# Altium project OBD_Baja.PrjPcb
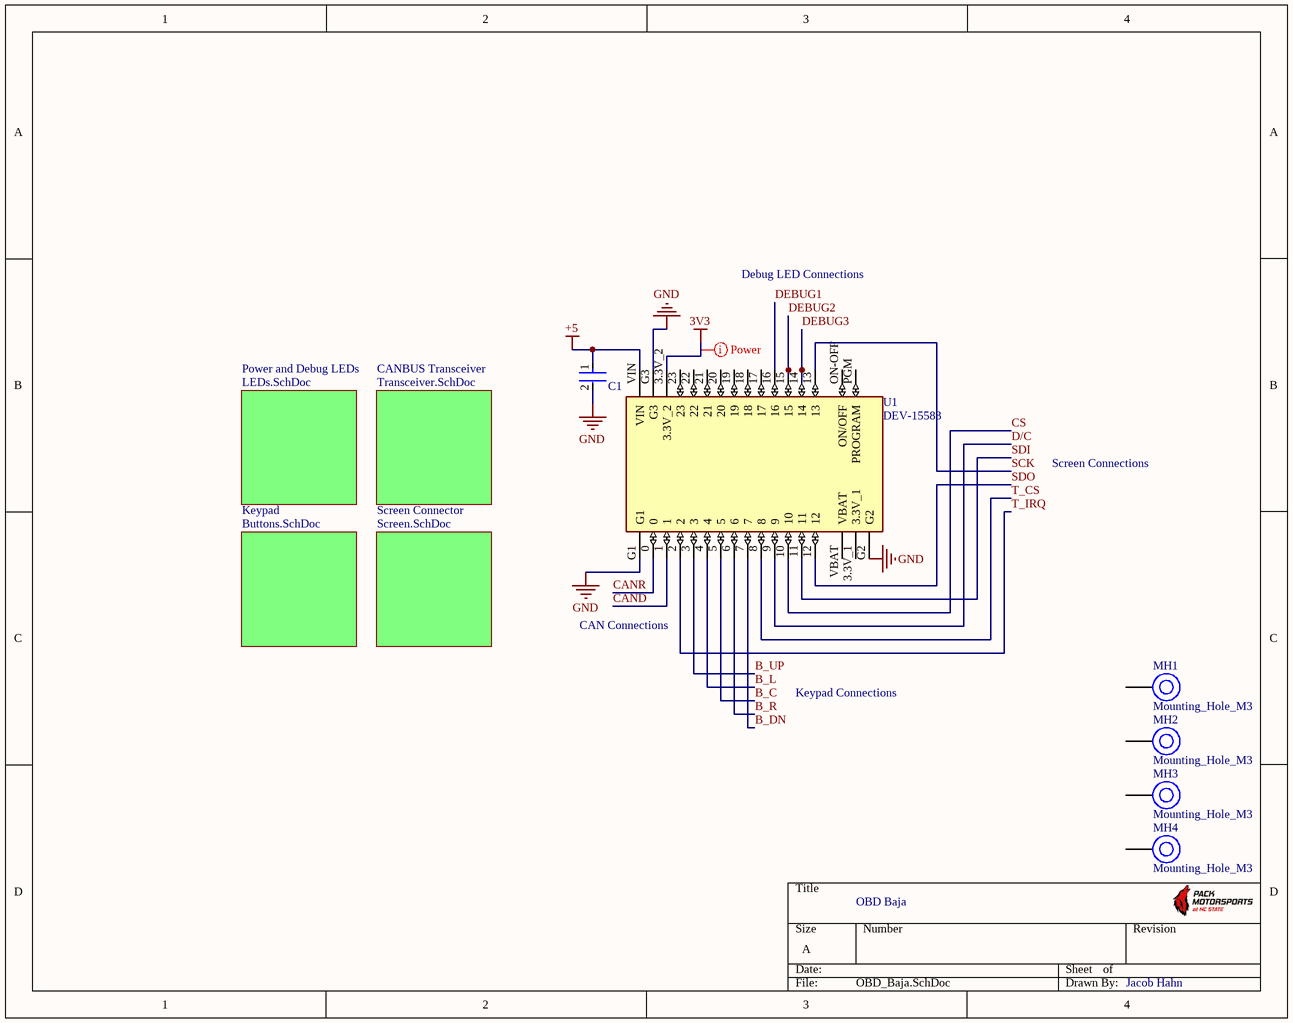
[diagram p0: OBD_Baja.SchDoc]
5 sheets, 34 parts. Net scope: global (net labels, ports and power ports of the same name join across sheets).
Board file: OBD_Baja.PcbDoc
Sheets:
  OBD_Baja.SchDoc
    CANBUS Transceiver = Transceiver.SchDoc
    Power and Debug LEDs = LEDs.SchDoc
    Keypad = Buttons.SchDoc
    Screen Connector = Screen.SchDoc

## Sheet OBD_Baja.SchDoc
size A; SheetNumber: 1; SheetTotal: 5

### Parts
C1  CL21B104KACNNNC  [FP-CL21-IPC_C]  (value not drawn)
MH1  Mounting_Hole_M3  [Mounting_Hole_M3]  (no BOM)
MH2  Mounting_Hole_M3  [Mounting_Hole_M3]  (no BOM)
MH3  Mounting_Hole_M3  [Mounting_Hole_M3]  (no BOM)
MH4  Mounting_Hole_M3  [Mounting_Hole_M3]  (no BOM)
U1  DEV-15583  [MODULE_DEV-15583]

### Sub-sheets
CANBUS Transceiver = Transceiver.SchDoc: no entries
Keypad = Buttons.SchDoc: no entries
Power and Debug LEDs = LEDs.SchDoc: no entries
Screen Connector = Screen.SchDoc: no entries

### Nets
3V3: U1.3.3V_2
+5: C1.1 U1.VIN
GND: C1.2 U1.G1 U1.G2 U1.G3
B_C: U1.5
B_DN: U1.7
B_L: U1.4
B_R: U1.6
B_UP: U1.3
CAND: U1.1
CANR: U1.0
CS: U1.10
D/C: U1.9
DEBUG1: U1.16
DEBUG2: U1.15
DEBUG3: U1.14
SCK: U1.13
SDI: U1.11
SDO: U1.12
T_CS: U1.8
T_IRQ: U1.2

Not connected (* = marked no-connect by the designer): MH1 1; MH2 1; MH3 1; MH4 1; U1 3.3V_1 17 18 19 20 21 22 23 ON-OFF(ON/OFF) PGM(PROGRAM) VBAT

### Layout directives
net class Power: 3V3

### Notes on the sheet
- Debug LED Connections
- Screen Connections
- CAN Connections
- Keypad Connections
- OBD Baja
- Jacob Hahn

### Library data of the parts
C1 = CMP-13271-002854-1: CL21 Series 0805 100nF 25V ±10% Tolerance X7R Multilayer Ceramic Chip Capacitor
MH1-MH4 = CMP-00001-4: Generic M3 Mounting Hole
U1 = CMP-301-000000-1: RT1062 Teensy 4.0 i.MX ARMÂ® CortexÂ®-M7 MPU Embedded Evaluation Board; MF: SparkFun Electronics

## Sheet Transceiver.SchDoc
size A; SheetNumber: 2; SheetTotal: 5
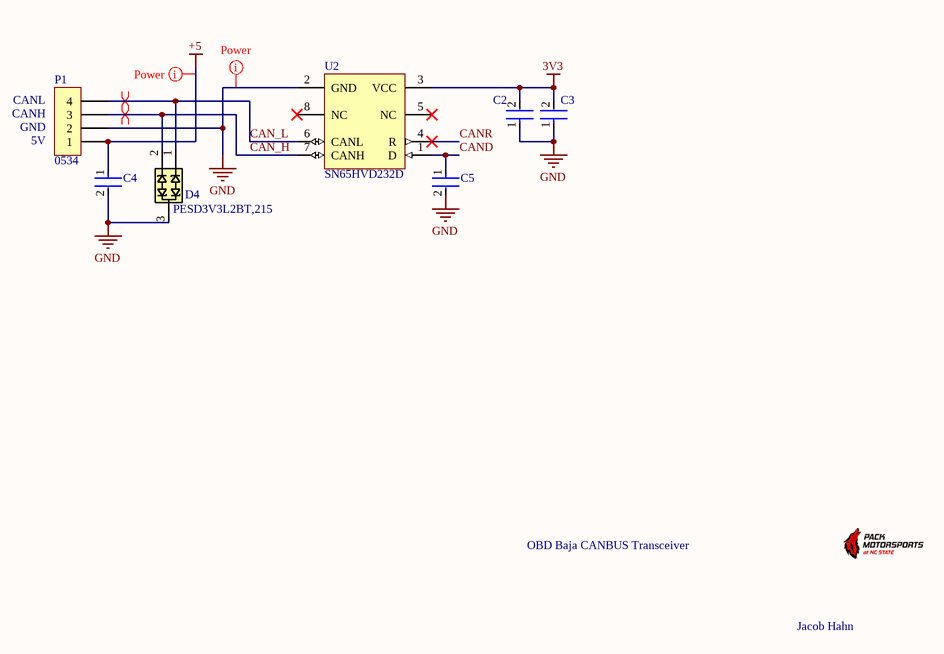
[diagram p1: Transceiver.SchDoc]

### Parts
C2  CL21B104KACNNNC  [FP-CL21-IPC_C]  (value not drawn)
C3  CL21B104KACNNNC  [FP-CL21-IPC_C]  (value not drawn)
C4  CL21A106KOQNNNE  [FP-CL21-IPC_B]  (value not drawn)
C5  CL21B103KAANNNC  [FP-CL21-IPC_C]  (value not drawn)
D4  PESD3V3L2BT,215  [SOT95P230X110-3N]
P1  0534  [0534260410]
U2  SN65HVD232D  [D0008A_L]

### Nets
3V3: C2.2 C3.2 U2.3(VCC)
+5: C4.1 P1.1
GND: C2.1 C3.1 C4.2 C5.2 D4.3 P1.2 U2.2(GND)
CAN_H: D4.2 P1.3 U2.7(CANH)
CAN_L: D4.1 P1.4 U2.6(CANL)
CAND: C5.1 U2.1(D)
CANR: U2.4(R)

Not connected (* = marked no-connect by the designer): U2 5(NC)* 8(NC)*

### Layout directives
net class Power: +5, GND
differential pair: CAN_H, CAN_L

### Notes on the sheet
- (near P1) CANL
- (near P1) CANH
- (near P1) GND
- (near P1) 5V
- OBD Baja CANBUS Transceiver
- Jacob Hahn

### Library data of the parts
C2 C3 = CMP-13271-002854-1: as C1 on sheet OBD_Baja
C4 = CMP-2000-06102-2: CL21 Series 0805 10uF 16V ±10% Tolerance X5R Multilayer Ceramic Chip Capacitor; Dielectric: X7R
C5 = CMP-13271-004188-1: CL21 Series 0805 10nF 25V ±10% Tolerance X7R Multilayer Ceramic Chip Capacitor; Voltage Rating (DC): 50V; Tolerance: 20%
D4 = CMP-00002-6: PESD3V3L2BT - Low capacitance double bidirectional ESD protection diode in SOT23
P1 = CMP-00000-3: 2.50mm Pitch Mini-Lock Wire-to-Board Header Right Angle Friction and Positive Lock 4 Circuits; Number of Contacts: 4; Pitch: 2.5mm; Contact Resistance: 20mR; Connector Type: Male Pin
U2 = CMP-0315-00073-2: 3.3 V CAN Transceiver, 17 mA, -40 to 85 degC, 8-pin SOIC (D), Green (RoHS & no Sb/Br); Manufacturer: Texas Instruments; Supply Voltage(s)(V): 3.3; Transient Pulse Protection(V): -25 to 25; ICC(Max)(mA): 17; Drivers Per Package: 1; Rating: Catalog

## Sheet LEDs.SchDoc
size A; SheetNumber: 3; SheetTotal: 5
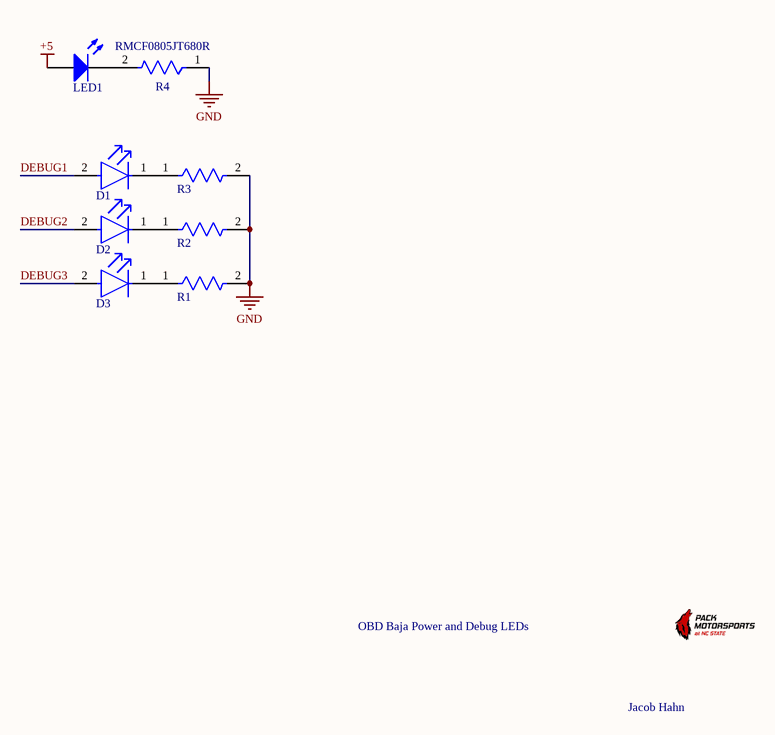
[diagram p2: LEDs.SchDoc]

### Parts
D1  LTST-C170GKT  [FP-LTST-C170GKT-MFG]  (value not drawn)
D2  LTST-C170GKT  [FP-LTST-C170GKT-MFG]  (value not drawn)
D3  LTST-C170GKT  [FP-LTST-C170GKT-MFG]  (value not drawn)
LED1  151031SS04000  [Type 3mm]  (value not drawn)
R1  RMCF0805JT240R  [FP-RMCF0805-IPC_A]  (value not drawn)
R2  RMCF0805JT240R  [FP-RMCF0805-IPC_A]  (value not drawn)
R3  RMCF0805JT240R  [FP-RMCF0805-IPC_A]  (value not drawn)
R4  RMCF0805JT680R  [FP-RMCF0805-IPC_C]

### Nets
+5: LED1.2(A)
GND: R1.2 R2.2 R3.2 R4.1
DEBUG1: D1.2(A)
DEBUG2: D2.2(A)
DEBUG3: D3.2(A)
NetD1_1: D1.1(C) R3.1
NetD2_1: D2.1(C) R2.1
NetD3_1: D3.1(C) R1.1
NetLED1_1: LED1.1(K) R4.2

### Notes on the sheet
- OBD Baja Power and Debug LEDs
- Jacob Hahn

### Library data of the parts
D1-D3 = CMP-1674-00002-6: LED GREEN CLEAR SMD; Dominant Wavelength: 569nm; Lens Style: Diffused; Forward Voltage: 2.1V; Number of Elements: 1; Wavelength: 565nm; Luminous Intensity: 6mcd; Test Current: 10mA; Power Dissipation: 100mW; Reverse Voltage: 5V; Forward Current: 30mA; Viewing Angle: 130°; Lens Color: Colorless
LED1 = CMP-1488-00005-1: THT LED round mono-color color lens, WL-TMRW, Super Red; Manufacturer: Wuerth Elektronik
R1-R3 = CMP-26527-005851-1: 240Ω ±5% 0.125W 0805 Thick Film Chip Resistor AEC-Q200 compliant; Temperature Coefficient: 200ppm/°C; Resistance: 240R; Max Power Dissipation: 125mW
R4 = CMP-26527-000032-1: 680Ω ±5% 0.125W 0805 Thick Film Chip Resistor AEC-Q200 compliant; Max Power Dissipation: 125mW; Resistance: 680R; Temperature Coefficient: 200ppm/°C

## Sheet Buttons.SchDoc
size A; SheetNumber: 4; SheetTotal: 5
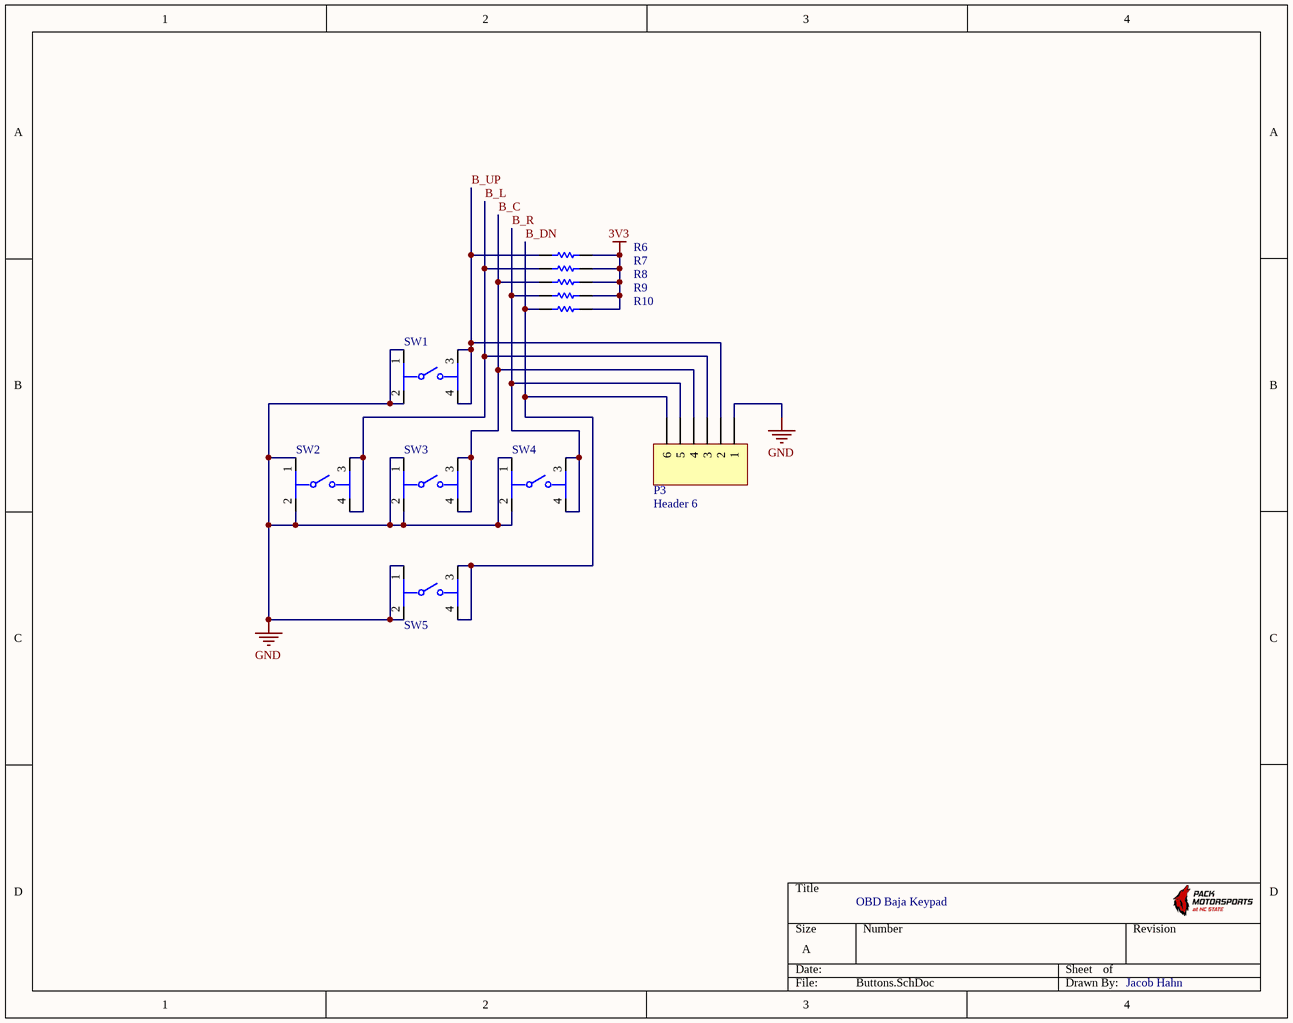
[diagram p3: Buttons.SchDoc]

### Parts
P3  Header 6  [HDR1X6]
R6  RC0805JR-0710KL  [RESC2013X60X35ML10T20]  (value not drawn)
R7  RC0805JR-0710KL  [RESC2013X60X35ML10T20]  (value not drawn)
R8  RC0805JR-0710KL  [RESC2013X60X35ML10T20]  (value not drawn)
R9  RC0805JR-0710KL  [RESC2013X60X35ML10T20]  (value not drawn)
R10  RC0805JR-0710KL  [RESC2013X60X35ML10T20]  (value not drawn)
SW1  KMR631NG ULC LFS  [FP-KMR631NG_ULC_LFS-MFG]  (value not drawn)
SW2  KMR631NG ULC LFS  [FP-KMR631NG_ULC_LFS-MFG]  (value not drawn)
SW3  KMR631NG ULC LFS  [FP-KMR631NG_ULC_LFS-MFG]  (value not drawn)
SW4  KMR631NG ULC LFS  [FP-KMR631NG_ULC_LFS-MFG]  (value not drawn)
SW5  KMR631NG ULC LFS  [FP-KMR631NG_ULC_LFS-MFG]  (value not drawn)

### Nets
3V3: R6.2 R7.2 R8.2 R9.2 R10.2
GND: P3.1 SW1.1 SW1.2 SW2.1 SW2.2 SW3.1 SW3.2 SW4.1 SW4.2 SW5.1 SW5.2
B_C: P3.4 R8.1 SW3.3 SW3.4
B_DN: P3.6 R10.1 SW5.3 SW5.4
B_L: P3.3 R7.1 SW2.3 SW2.4
B_R: P3.5 R9.1 SW4.3 SW4.4
B_UP: P3.2 R6.1 SW1.3 SW1.4

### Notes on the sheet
- OBD Baja Keypad
- Jacob Hahn

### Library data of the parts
P3 = Header 6: Header, 6-Pin
R6-R10 = CMP-2000-05025-1: Chip Resistor, 10 KOhm, +/- 5%, 0.125 W, -55 to 155 degC, 0805 (2012 Metric), RoHS, Tape and Reel; Manufacturer: Yageo; Resistor Element Type: ThickFilm; Voltage Rating: 150V; Product Range: RCSeries; SVHC: ToBeAdvised; Resistor Case Style: 0805[2012Metric]; Temperature Coefficient: ±100ppm/degC; Power Rating: 250mW; Resistance: 10kohm
SW1-SW5 = CMP-10040-000019-1: SWITCH TACTILE SPST-NO 50MA 32V; Mechanical Life: 150000Cycles; Actuator Type: Standard; Operating Force: 300gf; Switch Function: Off-Mom; Illumination Type: Non-Illuminated; Throw Configuration: SPST; Ratings: IP67

## Sheet Screen.SchDoc
size A; SheetNumber: 5; SheetTotal: 5
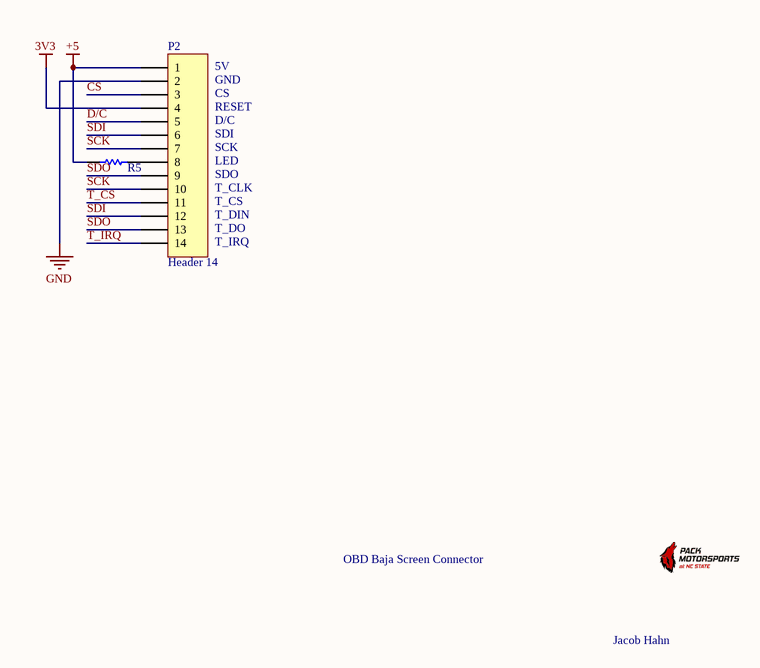
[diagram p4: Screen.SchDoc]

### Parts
P2  Header 14  [HDR1X14]
R5  RC0805FR-07100RL  [RESC2013X60X35ML10T20]  (value not drawn)

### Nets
3V3: P2.4
+5: P2.1 R5.1
GND: P2.2
CS: P2.3
D/C: P2.5
SCK: P2.7 P2.10
SDI: P2.6 P2.12
SDO: P2.9 P2.13
T_CS: P2.11
T_IRQ: P2.14
NetP2_8: P2.8 R5.2

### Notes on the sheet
- (near P2) 5V
- (near P2) GND
- (near P2) CS
- (near P2) RESET
- (near P2) D/C
- (near P2) SDI
- (near P2) SCK
- (near P2) LED
- (near P2) SDO
- (near P2) T_CLK
- (near P2) T_CS
- (near P2) T_DIN
- (near P2) T_DO
- (near P2) T_IRQ
- OBD Baja Screen Connector
- Jacob Hahn

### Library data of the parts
P2 = Header 14: Header, 14-Pin
R5 = CMP-2100-03669-1: Chip Resistor, 100 Ohm, +/-1%, 0.125 W, -55 to 155 degC, 0805 (2012 Metric), RoHS, Tape and Reel; Manufacturer: Yageo; Power Rating: 125mW; Resistance: 100Ohm; Voltage Rating: 150V; Tolerance: 1%; Temperature Coefficient: 100ppm/degreesC

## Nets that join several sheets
3V3: OBD_Baja (U1.3.3V_2), Transceiver (C2.2 C3.2 U2.3), Buttons (5 pins), Screen (P2.4)
+5: OBD_Baja (C1.1 U1.VIN), Transceiver (C4.1 P1.1), LEDs (LED1.2), Screen (P2.1 R5.1)
GND: OBD_Baja (C1.2 U1.G1 U1.G2 U1.G3), Transceiver (7 pins), LEDs (R1.2 R2.2 R3.2 R4.1), Buttons (11 pins), Screen (P2.2)
B_C: OBD_Baja (U1.5), Buttons (P3.4 R8.1 SW3.3 SW3.4)
B_DN: OBD_Baja (U1.7), Buttons (P3.6 R10.1 SW5.3 SW5.4)
B_L: OBD_Baja (U1.4), Buttons (P3.3 R7.1 SW2.3 SW2.4)
B_R: OBD_Baja (U1.6), Buttons (P3.5 R9.1 SW4.3 SW4.4)
B_UP: OBD_Baja (U1.3), Buttons (P3.2 R6.1 SW1.3 SW1.4)
CAND: OBD_Baja (U1.1), Transceiver (C5.1 U2.1)
CANR: OBD_Baja (U1.0), Transceiver (U2.4)
CS: OBD_Baja (U1.10), Screen (P2.3)
D/C: OBD_Baja (U1.9), Screen (P2.5)
DEBUG1: OBD_Baja (U1.16), LEDs (D1.2)
DEBUG2: OBD_Baja (U1.15), LEDs (D2.2)
DEBUG3: OBD_Baja (U1.14), LEDs (D3.2)
SCK: OBD_Baja (U1.13), Screen (P2.7 P2.10)
SDI: OBD_Baja (U1.11), Screen (P2.6 P2.12)
SDO: OBD_Baja (U1.12), Screen (P2.9 P2.13)
T_CS: OBD_Baja (U1.8), Screen (P2.11)
T_IRQ: OBD_Baja (U1.2), Screen (P2.14)

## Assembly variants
Internal Keypad: not fitted P3
External Keypad: not fitted R6 R7 R8 R9 R10 SW1 SW2 SW3 SW4 SW5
